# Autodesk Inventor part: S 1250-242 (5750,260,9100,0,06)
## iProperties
Category: PARTsolutions
Created: 2011-08
Part Number: S 1250-242 (5750,260,9100,0,06)
Catalog Web Link: www.cadenas.de
Description: 1250 Führungskanal - Führungskanal
Document SubType Name: Modeling
Designer: PARTsolutions
Density: 1 g/cm^3
NB: S 1250-242 (5750,260,9100,0,06)
NN: 1250 Führungskanal
NT: Führungskanal
NBSYN: $TYP.-$BI. ($LK.,$KR.,$LS.,$LV.,$ESP.$STEGV.)
LINA: S 1250-242 (5750,260,9100,0,06)
TYP: S 1250
BI: 242
BK: 291
LK: 5750
KR: 260
LS: 9100
LV: 0
STEGV: 6
LF: 4737.500
ESP: 0
PSTOL: 0.010
T: 125.000
LS2: 4550.000
DR: 83.186
LB: 1191.814
EASS: 0.000
VAR: 1.000
LKA: 5875.000
MOD1: 1.000
RX2: 520.000
HI: 69.000
HG: 94
TYP1: S1250
BIMIN: 101.000
BIMAX: 751.000
KRV: 145,200,220,260,300,340,380,420,460,500,540,600,700
LSMAX: 150000.000
BKMIN: 150.000
BKMAX: 800.000
BST: 267.000
BST1: 267.000
PIN: 18.800
KT: DUMMY
SUPPLIER: Kabelschlepp
ARTICLENO: S 1250-242 (5750,260,9100,0,06)
BOMINFO: S 1250-242 (5750,260,9100,0,06)
CREATOR: CADENAS GmbH
PSOL_IDENT_0: {\\10.0.0.251\ps_data\23d-libs\kabelschlepp\4_eketten_st\parts\1250_kabelkanal.prj},237 {VTYP=3D},{N
PSOL_IDENT_1: B=S 1250-242 (5750,260,9100,0,06)},{LINA=S 1250-242 (5750,260,9100,0,06)},{NN=1250 Führungskanal},{D
PSOL_IDENT_2: ATE=31.05.2007 07:52:20},{GEOMDATE=19.03.2007 11:05:00},{VERSION=},{LINEID=10},{LINESUBID=-1},{WBVAR
PSOL_IDENT_3: =BI,KR,LS,LV,STEGV,ESP}  {NB=S 1250-242 (5750,260,9100,0,06)},{LINA=S 1250-242 (5750,260,9100,0,06)}
PSOL_IDENT_4: ,{KT=DUMMY},{TYP=S 1250},{BI=242},{BK=291},{LK=5750},{KR=260},{LS=9100},{LV=0},{STEGV=6},{LF=4737.5}
PSOL_IDENT_5: ,{ESP=0},{PSTOL=0.010},{T=125.000},{LS2=4550},{DR=83.18591},{LB=1191.81409},{EASS=0},{VAR=1},{LKA=58
PSOL_IDENT_6: 75},{MOD1=1},{RX2=520},{NB1=},{HI=69},{HG=94},{TYP1=S1250},{BIMIN=101},{BIMAX=751},{KRV=145,200,220,
PSOL_IDENT_7: 260,300,340,380,420,460,500,540,600,700},{LSMAX=150000.000},{SV=-1000000015047466200000000000000.00}
PSOL_IDENT_8: ,{SV1=},{BKMIN=150},{BKMAX=800},{BST=267},{BST1=267},{PIN=18.8}
Title: S 1250-242 (5750,260,9100,0,06)
Author: Cadenas PARTsolutions
Comments: Führungskanal
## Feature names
1. Extrusion1
